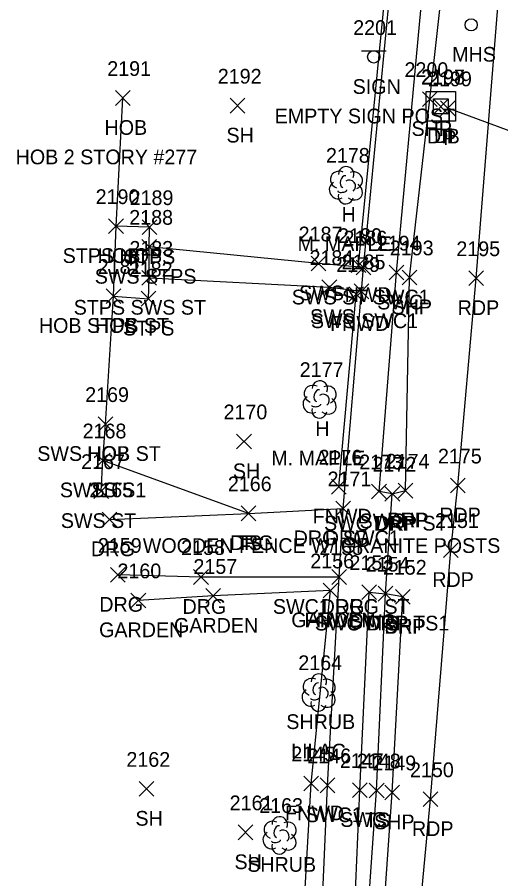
# Model space of a CAD drawing. Extents: x 1653908 to 1654393, y 539913 to 544256.
# Drawn here: x 1654026 to 1654091.7, y 541903.2 to 542020.2 of the extents above; entities that cross this region are included whole.
import ezdxf

# ---------------------------------------------------------------- set-up
doc = ezdxf.new("R2010")
doc.units = 0
for name, color, linetype in [('D_A', 7, 'Continuous'), ('D_I', 7, 'Continuous'), ('D_TIC', 7, 'Continuous'), ('DCP', 7, 'Continuous'), ('DS', 7, 'Continuous'), ('L_A', 7, 'Continuous'), ('L_C', 7, 'Continuous'), ('L_I', 7, 'Continuous'), ('L_TIC', 7, 'Continuous'), ('LAPB', 7, 'Continuous'), ('LBC', 7, 'Continuous'), ('LBF', 7, 'Continuous'), ('LELB', 7, 'Continuous'), ('LFNC', 7, 'Continuous'), ('LSH', 7, 'Continuous'), ('LTD', 7, 'Continuous'), ('P_A', 7, 'Continuous'), ('P_I', 7, 'Continuous'), ('P_TIC', 7, 'Continuous'), ('PET', 7, 'Continuous'), ('PSP', 7, 'Continuous'), ('R_A', 7, 'Continuous'), ('R_I', 7, 'Continuous'), ('R_TIC', 7, 'Continuous'), ('RDG', 7, 'Continuous'), ('RDP', 7, 'Continuous'), ('RSW', 7, 'Continuous'), ('S_A', 7, 'Continuous'), ('S_C', 7, 'Continuous'), ('S_I', 7, 'Continuous'), ('SSGN', 7, 'Continuous'), ('U_A', 7, 'Continuous'), ('USMH', 7, 'Continuous')]:
    doc.layers.add(name, color=color, linetype=linetype)

msp = doc.modelspace()

# ---------------------------------------------------------------- linework, layer by layer
at = {"layer": 'D_TIC'}
for points in [[(1654082.59, 542007.1), (1654084.59, 542009.1)], [(1654084.59, 542007.1), (1654082.59, 542009.1)], [(1654083.54, 542006.87), (1654085.54, 542008.87)], [(1654085.54, 542006.87), (1654083.54, 542008.87)]]:
    msp.add_lwpolyline(points, dxfattribs=at)
at = {"layer": 'DCP'}
msp.add_lwpolyline([(1654118.98, 541995.16), (1654084.54, 542007.87)], dxfattribs=at)
at = {"layer": 'DS'}
for p, q in [((1654081.58, 542010.14), (1654085.58, 542010.14)), ((1654081.58, 542006.14), (1654081.58, 542010.14)), ((1654085.58, 542010.14), (1654085.58, 542006.14)), ((1654082.58, 542007.14), (1654082.58, 542009.14)), ((1654082.58, 542009.14), (1654084.58, 542009.14)), ((1654084.58, 542009.14), (1654084.58, 542007.14)), ((1654083.59, 542008.14), (1654083.59, 542008.14)), ((1654083.59, 542008.14), (1654083.59, 542008.14)), ((1654084.58, 542007.14), (1654082.58, 542007.14)), ((1654085.58, 542006.14), (1654081.58, 542006.14))]:
    msp.add_line(p, q, dxfattribs=at)
at = {"layer": 'L_TIC'}
for points in [[(1654039.37, 542008.27), (1654041.37, 542010.27)], [(1654041.37, 542008.27), (1654039.37, 542010.27)], [(1654054.95, 542007.23), (1654056.95, 542009.23)], [(1654056.95, 542007.23), (1654054.95, 542009.23)], [(1654038.43, 541990.87), (1654040.43, 541992.87)], [(1654040.43, 541990.87), (1654038.43, 541992.87)], [(1654038.43, 541990.87), (1654040.43, 541992.87)], [(1654040.43, 541990.87), (1654038.43, 541992.87)], [(1654042.98, 541990.73), (1654044.98, 541992.73)], [(1654044.98, 541990.73), (1654042.98, 541992.73)], [(1654042.92, 541988.06), (1654044.92, 541990.06)], [(1654044.92, 541988.06), (1654042.92, 541990.06)], [(1654071.39, 541985.58), (1654073.39, 541987.58)], [(1654073.39, 541985.58), (1654071.39, 541987.58)], [(1654042.94, 541983.85), (1654044.94, 541985.85)], [(1654044.94, 541983.85), (1654042.94, 541985.85)], [(1654038.07, 541981.38), (1654040.07, 541983.38)], [(1654040.07, 541981.38), (1654038.07, 541983.38)], [(1654038.07, 541981.38), (1654040.07, 541983.38)], [(1654040.07, 541981.38), (1654038.07, 541983.38)], [(1654042.86, 541981.02), (1654044.86, 541983.02)], [(1654044.86, 541981.02), (1654042.86, 541983.02)], [(1654071.07, 541981.65), (1654073.07, 541983.65)], [(1654073.07, 541981.65), (1654071.07, 541983.65)], [(1654036.99, 541963.99), (1654038.99, 541965.99)], [(1654038.99, 541963.99), (1654036.99, 541965.99)], [(1654055.82, 541961.64), (1654057.82, 541963.64)], [(1654057.82, 541961.64), (1654055.82, 541963.64)], [(1654036.63, 541959.05), (1654038.63, 541961.05)], [(1654038.63, 541959.05), (1654036.63, 541961.05)], [(1654068.7, 541955.49), (1654070.7, 541957.49)], [(1654070.7, 541955.49), (1654068.7, 541957.49)], [(1654056.42, 541951.87), (1654058.42, 541953.87)], [(1654058.42, 541951.87), (1654056.42, 541953.87)], [(1654067.58, 541941.4), (1654069.58, 541943.4)], [(1654069.58, 541941.4), (1654067.58, 541943.4)], [(1654067.58, 541941.4), (1654069.58, 541943.4)], [(1654069.58, 541941.4), (1654067.58, 541943.4)], [(1654041.46, 541940.05), (1654043.46, 541942.05)], [(1654043.46, 541940.05), (1654041.46, 541942.05)], [(1654051.64, 541940.65), (1654053.64, 541942.65)], [(1654053.64, 541940.65), (1654051.64, 541942.65)], [(1654075.05, 541940.96), (1654077.05, 541942.96)], [(1654077.05, 541940.96), (1654075.05, 541942.96)], [(1654042.58, 541914.45), (1654044.58, 541916.45)], [(1654044.58, 541914.45), (1654042.58, 541916.45)], [(1654064.94, 541915.19), (1654066.94, 541917.19)], [(1654066.94, 541915.19), (1654064.94, 541917.19)], [(1654073.85, 541914.23), (1654075.85, 541916.23)], [(1654075.85, 541914.23), (1654073.85, 541916.23)], [(1654056.04, 541908.55), (1654058.04, 541910.55)], [(1654058.04, 541908.55), (1654056.04, 541910.55)]]:
    msp.add_lwpolyline(points, dxfattribs=at)
at = {"layer": 'LAPB'}
msp.add_lwpolyline([(1654068.58, 541942.4), (1654052.64, 541941.65), (1654042.46, 541941.05)], dxfattribs=at)
at = {"layer": 'LBC'}
msp.add_lwpolyline([(1654037.99, 541964.99), (1654039.07, 541982.38), (1654039.43, 541991.87), (1654040.37, 542009.27)], dxfattribs=at)
at = {"layer": 'LBF'}
msp.add_lwpolyline([(1654039.07, 541982.38), (1654043.86, 541982.02), (1654043.94, 541984.85), (1654043.92, 541989.06), (1654043.98, 541991.73), (1654039.43, 541991.87)], dxfattribs=at)
at = {"layer": 'LELB'}
for points in [[(1654057.42, 541952.87), (1654037.63, 541960.05)], [(1654071.55, 541868.41), (1654074.85, 541915.23), (1654076.05, 541941.96)]]:
    msp.add_lwpolyline(points, dxfattribs=at)
at = {"layer": 'LFNC'}
for points in [[(1654072.39, 541986.58), (1654076.79, 542031.31), (1654079.78, 542064.81)], [(1654069.7, 541956.49), (1654072.07, 541982.65)], [(1654050.94, 541892.63), (1654064.51, 541890.88), (1654065.94, 541916.19), (1654068.58, 541942.4)]]:
    msp.add_lwpolyline(points, dxfattribs=at)
at = {"layer": 'LSH'}
for p, q in [((1654066.94, 541928.58), (1654066.94, 541928.58)), ((1654066.94, 541928.58), (1654066.94, 541928.58)), ((1654061.63, 541909.19), (1654061.63, 541909.19)), ((1654061.63, 541909.19), (1654061.63, 541909.19))]:
    msp.add_line(p, q, dxfattribs=at)
for centre in [(1654066.99, 541930.02), (1654061.68, 541910.62)]:
    msp.add_arc(centre, 1.05, 335.5272, 180.9563, dxfattribs=at)
for centre, major_axis, ratio, start_param, end_param in [((1654066.15, 541929.25), (1.21, -0.51), 0.895232, 1.570796, 4.712389), ((1654067.99, 541929.17), (-1.14, -0.48), 0.949671, 1.570796, 4.712389), ((1654066.74, 541929.04), (-0.208, -0.792), 0.645439, 3.141593, 6.283185), ((1654067.44, 541928.42), (-0.5, 0.667), 0.989748, 3.141593, 6.283185), ((1654065.86, 541927.87), (0.58, -1.04), 0.959034, 3.141593, 6.283185), ((1654066.49, 541927.83), (-0.625, -0.083), 0.423636, 0, 3.141593), ((1654067.94, 541927.75), (-1.09, 0.79), 0.841452, 1.570796, 4.712389), ((1654066.94, 541927.08), (0.26, 1.06), 0.942809, 1.570796, 4.712389), ((1654060.84, 541909.85), (1.21, -0.51), 0.895232, 1.570796, 4.712389), ((1654061.43, 541909.64), (-0.208, -0.792), 0.645439, 3.141593, 6.283185), ((1654062.68, 541909.77), (-1.14, -0.48), 0.949671, 1.570796, 4.712389), ((1654060.55, 541908.48), (0.58, -1.04), 0.959034, 3.141593, 6.283185), ((1654062.13, 541909.02), (-0.5, 0.667), 0.989748, 3.141593, 6.283185), ((1654062.63, 541908.35), (-1.09, 0.79), 0.841452, 1.570796, 4.712389), ((1654061.18, 541908.44), (-0.625, -0.083), 0.423636, 0, 3.141593), ((1654061.63, 541907.69), (0.26, 1.06), 0.942809, 1.570796, 4.712389)]:
    msp.add_ellipse(centre, major_axis=major_axis, ratio=ratio, start_param=start_param, end_param=end_param, dxfattribs=at)
at = {"layer": 'LTD'}
for p, q in [((1654070.65, 541997.48), (1654070.65, 541997.48)), ((1654070.65, 541997.48), (1654070.65, 541997.48)), ((1654067.08, 541968.38), (1654067.08, 541968.38)), ((1654067.08, 541968.38), (1654067.08, 541968.38))]:
    msp.add_line(p, q, dxfattribs=at)
for centre in [(1654070.7, 541998.91), (1654067.13, 541969.82)]:
    msp.add_arc(centre, 1.05, 335.5272, 180.9563, dxfattribs=at)
for centre, major_axis, ratio, start_param, end_param in [((1654069.86, 541998.14), (1.21, -0.51), 0.895232, 1.570796, 4.712389), ((1654071.69, 541998.06), (-1.14, -0.48), 0.949671, 1.570796, 4.712389), ((1654070.44, 541997.93), (-0.208, -0.792), 0.645439, 3.141593, 6.283185), ((1654071.15, 541997.31), (-0.5, 0.667), 0.989748, 3.141593, 6.283185), ((1654069.57, 541996.77), (0.58, -1.04), 0.959034, 3.141593, 6.283185), ((1654071.65, 541996.64), (-1.09, 0.79), 0.841452, 1.570796, 4.712389), ((1654070.65, 541995.98), (0.26, 1.06), 0.942809, 1.570796, 4.712389), ((1654070.19, 541996.73), (-0.625, -0.083), 0.423636, 0, 3.141593), ((1654066.29, 541969.05), (1.21, -0.51), 0.895232, 1.570796, 4.712389), ((1654068.12, 541968.97), (-1.14, -0.48), 0.949671, 1.570796, 4.712389), ((1654066.87, 541968.84), (-0.208, -0.792), 0.645439, 3.141593, 6.283185), ((1654067.58, 541968.22), (-0.5, 0.667), 0.989748, 3.141593, 6.283185), ((1654066, 541967.67), (0.58, -1.04), 0.959034, 3.141593, 6.283185), ((1654066.63, 541967.63), (-0.625, -0.083), 0.423636, 0, 3.141593), ((1654068.08, 541967.55), (-1.09, 0.79), 0.841452, 1.570796, 4.712389), ((1654067.08, 541966.88), (0.26, 1.06), 0.942809, 1.570796, 4.712389)]:
    msp.add_ellipse(centre, major_axis=major_axis, ratio=ratio, start_param=start_param, end_param=end_param, dxfattribs=at)
at = {"layer": 'P_TIC'}
for points in [[(1654081.06, 542008.12), (1654083.06, 542010.12)], [(1654083.06, 542008.12), (1654081.06, 542010.12)], [(1654078.33, 541983.91), (1654080.33, 541985.91)], [(1654080.33, 541983.91), (1654078.33, 541985.91)], [(1654087.37, 541983.8), (1654089.37, 541985.8)], [(1654089.37, 541983.8), (1654087.37, 541985.8)], [(1654084.88, 541955.64), (1654086.88, 541957.64)], [(1654086.88, 541955.64), (1654084.88, 541957.64)], [(1654077.77, 541954.95), (1654079.77, 541956.95)], [(1654079.77, 541954.95), (1654077.77, 541956.95)], [(1654083.92, 541946.88), (1654085.92, 541948.88)], [(1654085.92, 541946.88), (1654083.92, 541948.88)], [(1654077.39, 541940.54), (1654079.39, 541942.54)], [(1654079.39, 541940.54), (1654077.39, 541942.54)], [(1654075.97, 541913.97), (1654077.97, 541915.97)], [(1654077.97, 541913.97), (1654075.97, 541915.97)], [(1654081.16, 541913.04), (1654083.16, 541915.04)], [(1654083.16, 541913.04), (1654081.16, 541915.04)]]:
    msp.add_lwpolyline(points, dxfattribs=at)
at = {"layer": 'PET'}
msp.add_lwpolyline([(1654079.78, 541659.55), (1654071.38, 541669.62), (1654062.1, 541680.77), (1654062.28, 541682.13), (1654062.95, 541688.2), (1654063.58, 541697.88), (1654065.97, 541728.28), (1654069.39, 541768.38), (1654071.19, 541795.88), (1654073.5, 541821.5), (1654077.02, 541859.14), (1654082.16, 541914.04), (1654084.92, 541947.88), (1654085.88, 541956.64), (1654088.37, 541984.8), (1654091.95, 542029.61), (1654095.3, 542063.75), (1654100.14, 542114.45), (1654103.13, 542154.15), (1654108.14, 542200.44), (1654110.74, 542235.38)], dxfattribs=at)
at = {"layer": 'PSP'}
for points in [[(1654078.77, 541955.95), (1654079.33, 541984.91), (1654082.06, 542009.12), (1654084.44, 542030.24), (1654088.47, 542064.73), (1654094.99, 542114.99), (1654098.59, 542154.95), (1654100.36, 542172.13), (1654102.93, 542200.54), (1654105.59, 542231.12), (1654106.16, 542236.32)], [(1654059.29, 541697.92), (1654062.43, 541729.2), (1654066.61, 541768.76), (1654068.98, 541796.43), (1654071.26, 541821.84), (1654073.12, 541859.77), (1654076.97, 541914.97), (1654078.39, 541941.54)]]:
    msp.add_lwpolyline(points, dxfattribs=at)
at = {"layer": 'R_TIC'}
for points in [[(1654042.92, 541988.06), (1654044.92, 541990.06)], [(1654044.92, 541988.06), (1654042.92, 541990.06)], [(1654065.94, 541985.8), (1654067.94, 541987.8)], [(1654067.94, 541985.8), (1654065.94, 541987.8)], [(1654072.08, 541985.24), (1654074.08, 541987.24)], [(1654074.08, 541985.24), (1654072.08, 541987.24)], [(1654072.08, 541985.24), (1654074.08, 541987.24)], [(1654074.08, 541985.24), (1654072.08, 541987.24)], [(1654076.56, 541984.56), (1654078.56, 541986.56)], [(1654078.56, 541984.56), (1654076.56, 541986.56)], [(1654042.94, 541983.85), (1654044.94, 541985.85)], [(1654044.94, 541983.85), (1654042.94, 541985.85)], [(1654067.42, 541982.59), (1654069.42, 541984.59)], [(1654069.42, 541982.59), (1654067.42, 541984.59)], [(1654071.79, 541982.02), (1654073.79, 541984.02)], [(1654073.79, 541982.02), (1654071.79, 541984.02)], [(1654071.79, 541982.02), (1654073.79, 541984.02)], [(1654073.79, 541982.02), (1654071.79, 541984.02)], [(1654036.99, 541963.99), (1654038.99, 541965.99)], [(1654038.99, 541963.99), (1654036.99, 541965.99)], [(1654036.63, 541959.05), (1654038.63, 541961.05)], [(1654038.63, 541959.05), (1654036.63, 541961.05)], [(1654036.43, 541954.88), (1654038.43, 541956.88)], [(1654038.43, 541954.88), (1654036.43, 541956.88)], [(1654074.17, 541954.84), (1654076.17, 541956.84)], [(1654076.17, 541954.84), (1654074.17, 541956.84)], [(1654075.98, 541954.53), (1654077.98, 541956.53)], [(1654077.98, 541954.53), (1654075.98, 541956.53)], [(1654075.98, 541954.53), (1654077.98, 541956.53)], [(1654077.98, 541954.53), (1654075.98, 541956.53)], [(1654077.77, 541954.95), (1654079.77, 541956.95)], [(1654079.77, 541954.95), (1654077.77, 541956.95)], [(1654056.42, 541951.87), (1654058.42, 541953.87)], [(1654058.42, 541951.87), (1654056.42, 541953.87)], [(1654069.31, 541952.54), (1654071.31, 541954.54)], [(1654071.31, 541952.54), (1654069.31, 541954.54)], [(1654069.31, 541952.54), (1654071.31, 541954.54)], [(1654071.31, 541952.54), (1654069.31, 541954.54)], [(1654037.54, 541951.05), (1654039.54, 541953.05)], [(1654039.54, 541951.05), (1654037.54, 541953.05)], [(1654038.67, 541943.51), (1654040.67, 541945.51)], [(1654040.67, 541943.51), (1654038.67, 541945.51)], [(1654049.98, 541943.22), (1654051.98, 541945.22)], [(1654051.98, 541943.22), (1654049.98, 541945.22)], [(1654068.75, 541943.22), (1654070.75, 541945.22)], [(1654070.75, 541943.22), (1654068.75, 541945.22)], [(1654068.75, 541943.22), (1654070.75, 541945.22)], [(1654070.75, 541943.22), (1654068.75, 541945.22)], [(1654072.84, 541941.17), (1654074.84, 541943.17)], [(1654074.84, 541941.17), (1654072.84, 541943.17)], [(1654075.05, 541940.96), (1654077.05, 541942.96)], [(1654077.05, 541940.96), (1654075.05, 541942.96)], [(1654075.05, 541940.96), (1654077.05, 541942.96)], [(1654077.05, 541940.96), (1654075.05, 541942.96)], [(1654077.39, 541940.54), (1654079.39, 541942.54)], [(1654079.39, 541940.54), (1654077.39, 541942.54)], [(1654067.18, 541914.93), (1654069.18, 541916.93)], [(1654069.18, 541914.93), (1654067.18, 541916.93)], [(1654071.55, 541914.29), (1654073.55, 541916.29)], [(1654073.55, 541914.29), (1654071.55, 541916.29)]]:
    msp.add_lwpolyline(points, dxfattribs=at)
at = {"layer": 'RDG'}
for points in [[(1654038.54, 541952.05), (1654057.42, 541952.87), (1654070.31, 541953.54)], [(1654069.75, 541944.22), (1654050.98, 541944.22), (1654039.67, 541944.51)]]:
    msp.add_lwpolyline(points, dxfattribs=at)
at = {"layer": 'RDP'}
for points in [[(1654076.98, 541955.53), (1654078.77, 541955.95)], [(1654078.39, 541941.54), (1654076.05, 541941.96)]]:
    msp.add_lwpolyline(points, dxfattribs=at)
at = {"layer": 'RSW'}
for points in [[(1654051.37, 541872.29), (1654052.46, 541871.5), (1654066.16, 541870.17), (1654068.18, 541915.93), (1654069.75, 541944.22), (1654070.31, 541953.54), (1654072.79, 541983.02), (1654073.08, 541986.24), (1654077.36, 542031.04), (1654080.59, 542065.12), (1654085.44, 542116.23), (1654086.21, 542120.5), (1654089.27, 542157.54), (1654090.31, 542166.74), (1654093.11, 542195.97), (1654093.6, 542201.46), (1654097.18, 542235.4)], [(1654068.64, 541821.64), (1654069.31, 541838.71), (1654070.52, 541867.73), (1654072.55, 541915.29), (1654073.84, 541942.17), (1654076.05, 541941.96), (1654076.98, 541955.53), (1654075.17, 541955.84), (1654077.56, 541985.56), (1654081.72, 542030.54), (1654085.05, 542064.96), (1654089.27, 542115.61), (1654093.43, 542156.15), (1654094.75, 542169), (1654097.8, 542200), (1654101.29, 542234.25)], [(1654073.08, 541986.24), (1654066.94, 541986.8), (1654043.92, 541989.06)], [(1654043.94, 541984.85), (1654068.42, 541983.59), (1654072.79, 541983.02)], [(1654037.43, 541955.88), (1654037.63, 541960.05), (1654037.99, 541964.99)]]:
    msp.add_lwpolyline(points, dxfattribs=at)
at = {"layer": 'SSGN'}
for p, q in [((1654072.8, 542015.69), (1654076.14, 542015.69)), ((1654074.45, 542014.85), (1654074.45, 542014.85))]:
    msp.add_line(p, q, dxfattribs=at)
msp.add_circle((1654074.45, 542014.85), 0.833, dxfattribs=at)
at = {"layer": 'USMH'}
for p, q in [((1654087.69, 542019.21), (1654087.69, 542019.21)), ((1654088.53, 542019.21), (1654088.53, 542019.21))]:
    msp.add_line(p, q, dxfattribs=at)
msp.add_circle((1654087.69, 542019.21), 0.833, dxfattribs=at)

# ---------------------------------------------------------------- texts
at = {"layer": 'D_A'}
for s, p in [('DIB', (1654081.69, 542003.1)), ('DI', (1654082.64, 542003.14)), ('P', (1654083.91, 542002.87))]:
    msp.add_text(s, height=2, dxfattribs=at).set_placement(p)
at = {"layer": 'D_I'}
for s, p in [('2197', (1654080.89, 542011.14)), ('2198', (1654080.9, 542011.1)), ('2199', (1654081.84, 542010.87))]:
    msp.add_text(s, height=2, dxfattribs=at).set_placement(p)
at = {"layer": 'L_A'}
for s, p in [('HOB', (1654037.87, 542004.27)), ('SH', (1654054.44, 542003.23)), ('H', (1654070.08, 541992.48)), ('STPS HOB', (1654032.18, 541986.87)), ('HOB', (1654036.94, 541986.87)), ('STPS', (1654040.5, 541986.73)), ('SWS STPS', (1654036.54, 541984.06)), ('FNWD', (1654068.86, 541981.58)), ('STPS SWS ST', (1654033.68, 541979.85)), ('HOB STPS ST', (1654028.95, 541977.38)), ('HOB', (1654036.57, 541977.38)), ('FNWD', (1654068.53, 541977.65)), ('STPS', (1654040.38, 541977.02)), ('H', (1654066.52, 541963.38)), ('HOB', (1654035.5, 541959.99)), ('SH', (1654055.31, 541957.64)), ('TS', (1654036.04, 541955.05)), ('FNWD', (1654066.16, 541951.49)), ('TS', (1654055.83, 541947.87)), ('GARDEN', (1654047.31, 541936.65)), ('GARDEN', (1654063.25, 541937.4)), ('FNWD', (1654065.05, 541937.4)), ('TS', (1654074.46, 541936.96)), ('GARDEN', (1654037.13, 541936.05)), ('SHRUB', (1654062.57, 541923.58)), ('FNWD', (1654062.4, 541911.19)), ('SH', (1654042.07, 541910.45)), ('TS', (1654073.26, 541910.23)), ('SH', (1654055.53, 541904.55)), ('SHRUB', (1654057.26, 541904.19))]:
    msp.add_text(s, height=2, dxfattribs=at).set_placement(p)
at = {"layer": 'L_C'}
for s, p in [('HOB 2 STORY #277', (1654025.79, 542000.27)), ('M. MAPLE', (1654064.1, 541988.48)), ('M. MAPLE', (1654060.53, 541959.38)), ('WOODEN FENCE W/ GRANITE POSTS', (1654043.07, 541947.49)), ('LILAC', (1654063.22, 541919.58))]:
    msp.add_text(s, height=2, dxfattribs=at).set_placement(p)
at = {"layer": 'L_I'}
for s, p in [('2191', (1654038.24, 542012.27)), ('2192', (1654053.26, 542011.23)), ('2178', (1654067.96, 542000.48)), ('2190', (1654036.66, 541994.87)), ('2190', (1654036.66, 541994.87)), ('2189', (1654041.28, 541994.73)), ('2188', (1654041.23, 541992.06)), ('2180', (1654069.61, 541989.58)), ('2183', (1654041.25, 541987.85)), ('2179', (1654069.36, 541985.65)), ('2181', (1654036.94, 541985.38)), ('2181', (1654036.94, 541985.38)), ('2182', (1654041.17, 541985.02)), ('2177', (1654064.39, 541971.38)), ('2169', (1654035.24, 541967.99)), ('2170', (1654054.04, 541965.64)), ('2168', (1654034.89, 541963.05)), ('2176', (1654066.95, 541959.49)), ('2166', (1654054.63, 541955.87)), ('2157', (1654049.95, 541944.65)), ('2156', (1654065.83, 541945.4)), ('2156', (1654065.83, 541945.4)), ('2154', (1654073.36, 541944.96)), ('2160', (1654039.63, 541944.05)), ('2164', (1654064.2, 541931.58)), ('2145', (1654063.25, 541919.19)), ('2162', (1654040.84, 541918.45)), ('2148', (1654072.16, 541918.23)), ('2161', (1654054.87, 541912.55)), ('2163', (1654058.89, 541912.19))]:
    msp.add_text(s, height=2, dxfattribs=at).set_placement(p)
at = {"layer": 'P_A'}
for s, p in [('SHP', (1654079.59, 542004.12)), ('SHP', (1654076.87, 541979.91)), ('RDP', (1654085.86, 541979.8)), ('RDP', (1654083.36, 541951.64)), ('SHP', (1654076.3, 541950.95)), ('RDP', (1654082.41, 541942.88)), ('SHP', (1654075.93, 541936.54)), ('SHP', (1654074.5, 541909.97)), ('RDP', (1654079.65, 541909.04))]:
    msp.add_text(s, height=2, dxfattribs=at).set_placement(p)
at = {"layer": 'P_I'}
for s, p in [('2200', (1654078.63, 542012.12)), ('2193', (1654076.64, 541987.91)), ('2195', (1654085.68, 541987.8)), ('2174', (1654076.08, 541958.95)), ('2175', (1654083.18, 541959.64)), ('2151', (1654082.79, 541950.88)), ('2152', (1654075.7, 541944.54)), ('2149', (1654074.27, 541917.97)), ('2150', (1654079.38, 541917.04))]:
    msp.add_text(s, height=2, dxfattribs=at).set_placement(p)
at = {"layer": 'R_A'}
for s, p in [('SWS STPS', (1654036.54, 541984.06)), ('SWS ST SWC1', (1654063.32, 541981.24)), ('SWS ST SWC1', (1654063.32, 541981.24)), ('SWS', (1654064.31, 541981.8)), ('STPS SWS ST', (1654033.68, 541979.85)), ('SWC', (1654074.92, 541980.56)), ('SWS', (1654065.79, 541978.59)), ('SWS SWC1', (1654065.92, 541978.02)), ('SWS SWC1', (1654065.92, 541978.02)), ('SWS HOB ST', (1654028.73, 541959.99)), ('SWS TS1', (1654031.8, 541955.05)), ('SWS ST', (1654031.93, 541950.88)), ('SWC DRP ST', (1654067.7, 541950.53)), ('SWC', (1654072.53, 541950.84)), ('DRP', (1654074.47, 541950.53)), ('DRP', (1654076.26, 541950.95)), ('DRG SWC1', (1654063.57, 541948.54)), ('DRG', (1654067.8, 541948.54)), ('DRG', (1654036.03, 541947.05)), ('DRG', (1654054.91, 541947.87)), ('DRG', (1654037.16, 541939.51)), ('DRG', (1654048.47, 541939.22)), ('SWC1 DRG ST', (1654060.75, 541939.22)), ('DRG', (1654067.24, 541939.22)), ('SWC DRP TS1', (1654066.44, 541936.96)), ('SWC', (1654071.21, 541937.17)), ('DRP', (1654073.54, 541936.96)), ('DRP', (1654075.88, 541936.54)), ('SWC1', (1654065.22, 541910.93)), ('SWC', (1654069.91, 541910.29))]:
    msp.add_text(s, height=2, dxfattribs=at).set_placement(p)
at = {"layer": 'R_I'}
for s, p in [('2188', (1654041.23, 541992.06)), ('2187', (1654064.25, 541989.8)), ('2186', (1654070.34, 541989.24)), ('2186', (1654070.34, 541989.24)), ('2183', (1654041.25, 541987.85)), ('2194', (1654074.87, 541988.56)), ('2184', (1654065.73, 541986.59)), ('2185', (1654070.09, 541986.02)), ('2185', (1654070.09, 541986.02)), ('2169', (1654035.24, 541967.99)), ('2168', (1654034.89, 541963.05)), ('2167', (1654034.69, 541958.88)), ('2173', (1654072.48, 541958.84)), ('2174', (1654076.08, 541958.95)), ('2172', (1654074.29, 541958.53)), ('2172', (1654074.29, 541958.53)), ('2171', (1654068.18, 541956.54)), ('2171', (1654068.18, 541956.54)), ('2166', (1654054.63, 541955.87)), ('2165', (1654035.8, 541955.05)), ('2159', (1654036.97, 541947.51)), ('2158', (1654048.28, 541947.22)), ('2155', (1654067.06, 541947.22)), ('2155', (1654067.06, 541947.22)), ('2153', (1654071.15, 541945.17)), ('2154', (1654073.36, 541944.96)), ('2154', (1654073.36, 541944.96)), ('2152', (1654075.7, 541944.54)), ('2146', (1654065.43, 541918.93)), ('2147', (1654069.85, 541918.29))]:
    msp.add_text(s, height=2, dxfattribs=at).set_placement(p)
at = {"layer": 'S_A'}
msp.add_text('SIGN', height=2, dxfattribs=at).set_placement((1654071.59, 542009.83))
at = {"layer": 'S_C'}
msp.add_text('EMPTY SIGN POST', height=2, dxfattribs=at).set_placement((1654060.99, 542005.83))
at = {"layer": 'S_I'}
msp.add_text('2201', height=2, dxfattribs=at).set_placement((1654071.66, 542017.83))
at = {"layer": 'U_A'}
msp.add_text('MHS', height=2, dxfattribs=at).set_placement((1654085.11, 542014.21))

doc.saveas('drawing.dxf')
